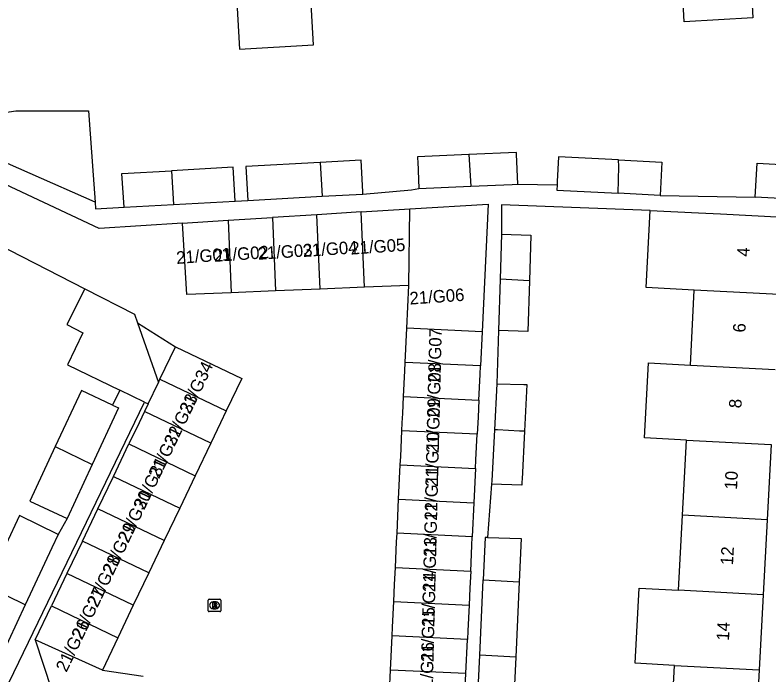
# Model space of a CAD drawing. Extents: x 163010 to 163853, y 382793 to 383982.
# Drawn here: x 163436.2 to 163496.4, y 383479.9 to 383532.5 of the extents above; entities that cross this region are included whole.
import ezdxf

# ---------------------------------------------------------------- set-up
doc = ezdxf.new("R2010")
doc.units = 0
for name, color, linetype in [('IMGEO_Muur', 7, 'Continuous'), ('IMGEO_Pand', 7, 'Continuous'), ('IMGEO_Pand_nummerreeks', 7, 'Continuous'), ('IMGEO_Rijbaan_lokaal_onverhard', 7, 'Continuous'), ('IMGEO_Rioolput', 7, 'Continuous'), ('IMGEO_Voetpad_open', 7, 'Continuous')]:
    doc.layers.add(name, color=color, linetype=linetype)

msp = doc.modelspace()

# ---------------------------------------------------------------- linework, layer by layer
at = {"layer": 'IMGEO_Muur'}
msp.add_lwpolyline([(163433.726, 383514.797), (163441.793, 383510.691)], dxfattribs=at)
at = {"layer": 'IMGEO_Pand'}
for points in [[(163495.553, 383535.925), (163494.936, 383535.89), (163495.138, 383532.314), (163489.66, 383532.005), (163489.458, 383535.581)], [(163453.922, 383533.576), (163454.134, 383529.824), (163460.057, 383530.158), (163459.845, 383533.91)], [(163429.633, 383526.219), (163433.296, 383524.445), (163436.265, 383524.895), (163442.07, 383524.895), (163442.446, 383519.77), (163442.604, 383517.614)], [(163442.604, 383517.614), (163432.199, 383522.177), (163428.534, 383523.951)], [(163472.461, 383521.405), (163468.358, 383521.219), (163468.365, 383521.062), (163468.374, 383520.849), (163468.473, 383518.68)], [(163476.376, 383519.039), (163476.268, 383521.421), (163476.261, 383521.578), (163472.461, 383521.405)], [(163472.461, 383521.405), (163472.604, 383518.868)], [(163460.587, 383520.767), (163454.65, 383520.441), (163454.805, 383517.746)], [(163463.999, 383518.252), (163463.989, 383518.439), (163463.851, 383520.946), (163460.587, 383520.767)], [(163460.587, 383520.767), (163460.739, 383518.073)], [(163484.394, 383520.983), (163479.614, 383521.229), (163479.512, 383519.254), (163479.498, 383518.987)], [(163484.389, 383518.307), (163484.425, 383520.438), (163484.394, 383520.983)], [(163484.394, 383520.983), (163487.871, 383520.805), (163487.733, 383518.136)], [(163453.796, 383517.691), (163453.643, 383520.385), (163448.714, 383520.114)], [(163495.326, 383518.001), (163495.471, 383520.705), (163499.302, 383520.499)], [(163444.931, 383517.204), (163444.733, 383519.896), (163448.714, 383520.114)], [(163448.714, 383520.114), (163448.866, 383517.42)], [(163472.604, 383518.868), (163475.909, 383519.018), (163476.376, 383519.039)], [(163479.498, 383518.987), (163479.476, 383518.56), (163484.389, 383518.307)], [(163468.473, 383518.68), (163472.604, 383518.868)], [(163454.805, 383517.746), (163460.739, 383518.073)], [(163460.739, 383518.073), (163463.999, 383518.252)], [(163487.733, 383518.136), (163484.389, 383518.307)], [(163499.398, 383517.783), (163495.326, 383518.001)], [(163444.931, 383517.204), (163448.866, 383517.42)], [(163448.866, 383517.42), (163453.796, 383517.691)], [(163467.755, 383517.057), (163474.005, 383517.441), (163473.517, 383507.261)], [(163460.326, 383516.6), (163456.785, 383516.382)], [(163463.867, 383516.818), (163460.326, 383516.6)], [(163460.57, 383510.666), (163460.326, 383516.6)], [(163463.867, 383516.818), (163467.755, 383517.057)], [(163464.114, 383510.811), (163463.867, 383516.818)], [(163467.658, 383510.957), (163467.755, 383517.057)], [(163490.462, 383510.592), (163486.618, 383510.789), (163486.932, 383516.935)], [(163486.932, 383516.935), (163490.788, 383516.738), (163492.562, 383516.66), (163497.554, 383516.392)], [(163449.585, 383515.939), (163453.243, 383516.164)], [(163453.481, 383510.375), (163449.937, 383510.229), (163449.585, 383515.939)], [(163453.243, 383516.164), (163454.573, 383516.246), (163456.785, 383516.382)], [(163453.243, 383516.164), (163453.481, 383510.375)], [(163456.785, 383516.382), (163457.025, 383510.52)], [(163475.054, 383515.037), (163474.944, 383511.459)], [(163475.054, 383515.037), (163477.418, 383514.964), (163477.296, 383511.334)], [(163474.944, 383511.459), (163474.819, 383507.361)], [(163477.296, 383511.334), (163477.16, 383507.289), (163474.819, 383507.361)], [(163477.296, 383511.334), (163474.944, 383511.459)], [(163441.793, 383510.691), (163440.342, 383507.84), (163441.639, 383507.18), (163440.404, 383504.631), (163444.584, 383502.605)], [(163441.793, 383510.691), (163445.756, 383508.673), (163446.001, 383507.968)], [(163457.025, 383510.52), (163453.481, 383510.375)], [(163460.57, 383510.666), (163457.025, 383510.52)], [(163464.114, 383510.811), (163460.57, 383510.666)], [(163467.658, 383510.957), (163464.114, 383510.811)], [(163467.496, 383507.546), (163467.658, 383510.957)], [(163490.145, 383504.601), (163490.462, 383510.592)], [(163497.226, 383510.232), (163490.462, 383510.592)], [(163446.001, 383507.968), (163447.658, 383503.202)], [(163467.367, 383504.818), (163467.496, 383507.546)], [(163473.517, 383507.261), (163467.496, 383507.546)], [(163473.517, 383507.261), (163473.386, 383504.532)], [(163447.787, 383503.472), (163449.03, 383506.063)], [(163449.03, 383506.063), (163454.312, 383503.53), (163453.076, 383500.944)], [(163467.237, 383502.089), (163467.334, 383504.136), (163467.367, 383504.818)], [(163473.386, 383504.532), (163467.367, 383504.818)], [(163473.255, 383501.804), (163473.354, 383503.85), (163473.386, 383504.532)], [(163489.827, 383498.609), (163486.482, 383498.786), (163486.8, 383504.778), (163490.145, 383504.601)], [(163490.145, 383504.601), (163496.906, 383504.241)], [(163447.658, 383503.202), (163447.787, 383503.472)], [(163447.787, 383503.472), (163453.076, 383500.944)], [(163446.846, 383501.509), (163447.658, 383503.202)], [(163474.684, 383503.113), (163474.493, 383499.441)], [(163474.684, 383503.113), (163476.851, 383503.047), (163477.093, 383503.039), (163476.899, 383499.314)], [(163444.007, 383501.414), (163441.51, 383502.579), (163439.415, 383498.089)], [(163446.555, 383501.65), (163444.584, 383502.605)], [(163467.108, 383499.361), (163467.138, 383500), (163467.172, 383500.725), (163467.237, 383502.089)], [(163467.237, 383502.089), (163473.255, 383501.804)], [(163446.846, 383501.509), (163446.548, 383500.887)], [(163446.555, 383501.65), (163446.846, 383501.509)], [(163473.255, 383501.804), (163473.19, 383500.44), (163473.169, 383500), (163473.125, 383499.075)], [(163444.007, 383501.414), (163444.487, 383501.19), (163442.372, 383496.654)], [(163446.548, 383500.887), (163446.123, 383500), (163445.31, 383498.302)], [(163451.84, 383498.358), (163446.548, 383500.887)], [(163453.076, 383500.944), (163452.625, 383500), (163451.84, 383498.358)], [(163466.978, 383496.632), (163467.011, 383497.315), (163467.108, 383499.361)], [(163473.125, 383499.075), (163467.108, 383499.361)], [(163472.994, 383496.347), (163473.026, 383497.029), (163473.125, 383499.075)], [(163474.493, 383499.441), (163474.279, 383495.349), (163474.266, 383495.094)], [(163476.899, 383499.314), (163476.7, 383495.502), (163476.688, 383495.275), (163476.685, 383495.216), (163476.675, 383495.02), (163474.266, 383495.094)], [(163476.899, 383499.314), (163476.725, 383499.323), (163476.506, 383499.335), (163474.754, 383499.427), (163474.493, 383499.441)], [(163489.51, 383492.618), (163489.827, 383498.609)], [(163489.827, 383498.609), (163496.587, 383498.249)], [(163439.415, 383498.089), (163437.388, 383493.743), (163440.366, 383492.354)], [(163439.415, 383498.089), (163442.372, 383496.654)], [(163444.072, 383495.717), (163445.31, 383498.302)], [(163445.31, 383498.302), (163450.604, 383495.772)], [(163451.84, 383498.358), (163450.604, 383495.772)], [(163496.587, 383498.249), (163496.267, 383492.258)], [(163442.372, 383496.654), (163440.366, 383492.354)], [(163466.849, 383493.904), (163466.978, 383496.632)], [(163466.978, 383496.632), (163472.994, 383496.347)], [(163472.994, 383496.347), (163472.863, 383493.619)], [(163442.834, 383493.132), (163444.072, 383495.717)], [(163444.072, 383495.717), (163449.367, 383493.186)], [(163450.604, 383495.772), (163449.367, 383493.186)], [(163466.719, 383491.176), (163466.849, 383493.904)], [(163466.849, 383493.904), (163472.863, 383493.619)], [(163441.596, 383490.547), (163442.834, 383493.132)], [(163448.131, 383490.6), (163442.834, 383493.132)], [(163449.367, 383493.186), (163448.131, 383490.6)], [(163472.863, 383493.619), (163472.732, 383490.89)], [(163439.646, 383491.086), (163436.559, 383492.584), (163435.474, 383490.258), (163433.072, 383491.378), (163431.554, 383488.123), (163434.068, 383486.902)], [(163489.193, 383486.626), (163489.51, 383492.618)], [(163496.267, 383492.258), (163489.51, 383492.618)], [(163496.267, 383492.258), (163495.948, 383486.266)], [(163439.646, 383491.086), (163439.14, 383490.003), (163437.025, 383485.467)], [(163466.59, 383488.447), (163466.687, 383490.493), (163466.719, 383491.176)], [(163472.732, 383490.89), (163466.719, 383491.176)], [(163472.601, 383488.162), (163472.699, 383490.208), (163472.732, 383490.89)], [(163473.954, 383490.842), (163473.765, 383490.848), (163473.606, 383487.448)], [(163473.954, 383490.842), (163476.642, 383490.76), (163476.479, 383487.295)], [(163441.596, 383490.547), (163440.358, 383487.962)], [(163446.895, 383488.014), (163441.596, 383490.547)], [(163448.131, 383490.6), (163446.895, 383488.014)], [(163466.46, 383485.719), (163466.525, 383487.083), (163466.59, 383488.447)], [(163466.59, 383488.447), (163472.601, 383488.162)], [(163440.358, 383487.962), (163439.12, 383485.377)], [(163445.659, 383485.428), (163440.358, 383487.962)], [(163446.895, 383488.014), (163445.659, 383485.428)], [(163472.601, 383488.162), (163472.536, 383486.797), (163472.47, 383485.433)], [(163473.324, 383481.444), (163473.606, 383487.448)], [(163473.606, 383487.448), (163476.479, 383487.295)], [(163476.479, 383487.295), (163476.197, 383481.291)], [(163437.025, 383485.467), (163434.068, 383486.902)], [(163488.875, 383480.633), (163485.742, 383480.799), (163486.06, 383486.793), (163489.193, 383486.626)], [(163495.948, 383486.266), (163489.193, 383486.626)], [(163495.948, 383486.266), (163495.629, 383480.274)], [(163437.025, 383485.467), (163435.019, 383481.167)], [(163437.823, 383482.669), (163439.12, 383485.377)], [(163439.12, 383485.377), (163444.422, 383482.842)], [(163445.659, 383485.428), (163444.422, 383482.842)], [(163466.33, 383482.99), (163466.363, 383483.672), (163466.46, 383485.719)], [(163466.46, 383485.719), (163472.47, 383485.433)], [(163472.47, 383485.433), (163472.372, 383483.387), (163472.339, 383482.705)], [(163444.422, 383482.842), (163443.186, 383480.256)], [(163466.201, 383480.262), (163466.33, 383482.99)], [(163472.339, 383482.705), (163466.33, 383482.99)], [(163443.186, 383480.256), (163437.823, 383482.669)], [(163437.823, 383482.669), (163440.453, 383474.663), (163445.576, 383473.9)], [(163472.208, 383479.976), (163472.339, 383482.705)], [(163473.042, 383475.438), (163473.324, 383481.444)], [(163476.197, 383481.291), (163473.324, 383481.444)], [(163476.197, 383481.291), (163475.915, 383475.285)], [(163488.558, 383474.642), (163488.875, 383480.633)], [(163488.875, 383480.633), (163495.629, 383480.274)], [(163443.186, 383480.256), (163446.451, 383479.77)], [(163465.171, 383470.981), (163471.73, 383470.004), (163472.208, 383479.976)], [(163466.039, 383476.851), (163466.201, 383480.262)], [(163472.208, 383479.976), (163466.201, 383480.262)], [(163495.629, 383480.274), (163495.309, 383474.283)]]:
    msp.add_lwpolyline(points, dxfattribs=at)
at = {"layer": 'IMGEO_Rijbaan_lokaal_onverhard'}
for points in [[(163449.585, 383515.939), (163442.932, 383515.502), (163427.893, 383522.56)], [(163433.726, 383514.797), (163441.793, 383510.691)], [(163446.001, 383507.968), (163449.03, 383506.063)]]:
    msp.add_lwpolyline(points, dxfattribs=at)
at = {"layer": 'IMGEO_Rioolput'}
for p, q in [((163451.647, 383484.999), (163451.647, 383485.851)), ((163451.722, 383485.925), (163452.574, 383485.925)), ((163452.648, 383485.851), (163452.648, 383484.999)), ((163452.135, 383485.705), (163452.16, 383485.705)), ((163452.574, 383484.925), (163451.722, 383484.925)), ((163452.158, 383485.145), (163452.133, 383485.145))]:
    msp.add_line(p, q, dxfattribs=at)
for points in [[(163451.647, 383484.999), (163451.647, 383485.851)], [(163451.722, 383485.925), (163452.574, 383485.925)], [(163452.648, 383485.851), (163452.648, 383484.999)], [(163452.236, 383485.623), (163451.984, 383485.625), (163451.984, 383485.225)], [(163451.984, 383485.225), (163452.108, 383485.225), (163452.108, 383485.387), (163452.119, 383485.387)], [(163452.162, 383485.544), (163452.108, 383485.544), (163452.108, 383485.463)], [(163452.108, 383485.463), (163452.16, 383485.463)], [(163452.166, 383485.358), (163452.237, 383485.225), (163452.377, 383485.225), (163452.312, 383485.351)], [(163452.574, 383484.925), (163451.722, 383484.925)]]:
    msp.add_lwpolyline(points, dxfattribs=at)
for centre, radius, start, end in [((163451.724, 383485.849), 0.0765, 91.55205, 178.44795), ((163451.724, 383485.849), 0.0765, 91.55205, 178.44795), ((163452.572, 383485.849), 0.0765, 1.55205, 88.44795), ((163452.572, 383485.849), 0.0765, 1.55205, 88.44795), ((163452.118, 383485.334), 0.0533, 26.02933, 88.69889), ((163452.144, 383485.652), 0.19, 274.7715, 282.96867), ((163452.168, 383485.448), 0.0964, 77.00612, 93.18647), ((163452.182, 383485.505), 0.0378, 276.66336, 79.67722), ((163452.235, 383485.513), 0.109, 350.36119, 89.41601), ((163452.233, 383485.513), 0.112, 277.58423, 350.98172), ((163452.217, 383485.298), 0.108, 29.51342, 73.79051), ((163451.724, 383485.001), 0.0765, 181.55205, 268.44795), ((163451.724, 383485.001), 0.0765, 181.55205, 268.44795), ((163452.572, 383485.001), 0.0765, 271.55205, 358.44795), ((163452.572, 383485.001), 0.0765, 271.55205, 358.44795)]:
    msp.add_arc(centre, radius, start, end, dxfattribs=at)
for centre, major_axis, ratio, start_param, end_param in [((163452.134, 383485.425), (-0.387, 0.002), 0.722429, 4.712389, 7.853982), ((163452.159, 383485.425), (-0.39, 0.002), 0.717154, 1.570796, 4.712389)]:
    msp.add_ellipse(centre, major_axis=major_axis, ratio=ratio, start_param=start_param, end_param=end_param, dxfattribs=at)
at = {"layer": 'IMGEO_Voetpad_open'}
for points in [[(163476.376, 383519.039), (163479.498, 383518.987)], [(163463.999, 383518.252), (163467.872, 383518.597), (163468.473, 383518.68)], [(163453.796, 383517.691), (163454.803, 383517.746), (163454.805, 383517.746)], [(163487.733, 383518.136), (163495.326, 383518.001)], [(163442.604, 383517.614), (163442.644, 383517.078), (163444.931, 383517.204)], [(163486.932, 383516.935), (163475.059, 383517.395), (163475.054, 383515.037)], [(163474.819, 383507.361), (163474.684, 383503.113)], [(163444.584, 383502.605), (163444.007, 383501.414)], [(163428.344, 383452.674), (163431.455, 383470.492), (163446.555, 383501.65)], [(163474.266, 383495.094), (163473.954, 383490.842)], [(163440.366, 383492.354), (163439.646, 383491.086)]]:
    msp.add_lwpolyline(points, dxfattribs=at)

# ---------------------------------------------------------------- texts
at = {"layer": 'IMGEO_Pand_nummerreeks'}
for s, rotation, p in [('21/G02', 4.04589, (163452.132, 383512.833)), ('21/G03', 4.04589, (163455.623, 383512.999)), ('21/G04', 4.04589, (163459.217, 383513.221)), ('21/G05', 4.04589, (163463.033, 383513.414)), ('21/G01', 4.04589, (163449.121, 383512.668)), ('4', 86.94804, (163494.862, 383513.228)), ('21/G06', 4.04589, (163467.754, 383509.425)), ('21/G07', 88.55761, (163470.191, 383503.159)), ('6', 86.94804, (163494.539, 383507.18)), ('21/G34', 64.40858, (163450.177, 383500.614)), ('21/G08', 88.55761, (163470.121, 383500.367)), ('21/G33', 64.40858, (163448.945, 383498.042)), ('21/G09', 88.55761, (163470.05, 383497.565)), ('8', 86.94635, (163494.218, 383501.136)), ('21/G32', 64.40858, (163447.71, 383495.463)), ('21/G10', 88.55761, (163469.982, 383494.868)), ('21/G31', 64.40858, (163446.528, 383492.995)), ('21/G11', 88.55761, (163469.915, 383492.179)), ('10', 86.94881, (163493.87, 383494.639)), ('21/G30', 64.40858, (163445.25, 383490.326)), ('21/G12', 88.55761, (163469.841, 383489.268)), ('21/G29', 64.40858, (163444.015, 383487.747)), ('21/G13', 88.55761, (163469.771, 383486.479)), ('12', 86.94881, (163493.549, 383488.608)), ('21/G28', 64.40858, (163442.785, 383485.18)), ('21/G14', 88.55761, (163469.701, 383483.684)), ('21/G27', 64.40858, (163441.552, 383482.604)), ('21/G15', 88.55761, (163469.63, 383480.888)), ('21/G26', 64.40858, (163440.32, 383480.032)), ('14', 86.94635, (163493.228, 383482.587)), ('21/G16', 88.55761, (163469.56, 383478.093))]:
    msp.add_text(s, height=1, rotation=rotation, dxfattribs=at).set_placement(p)

doc.saveas('drawing.dxf')
